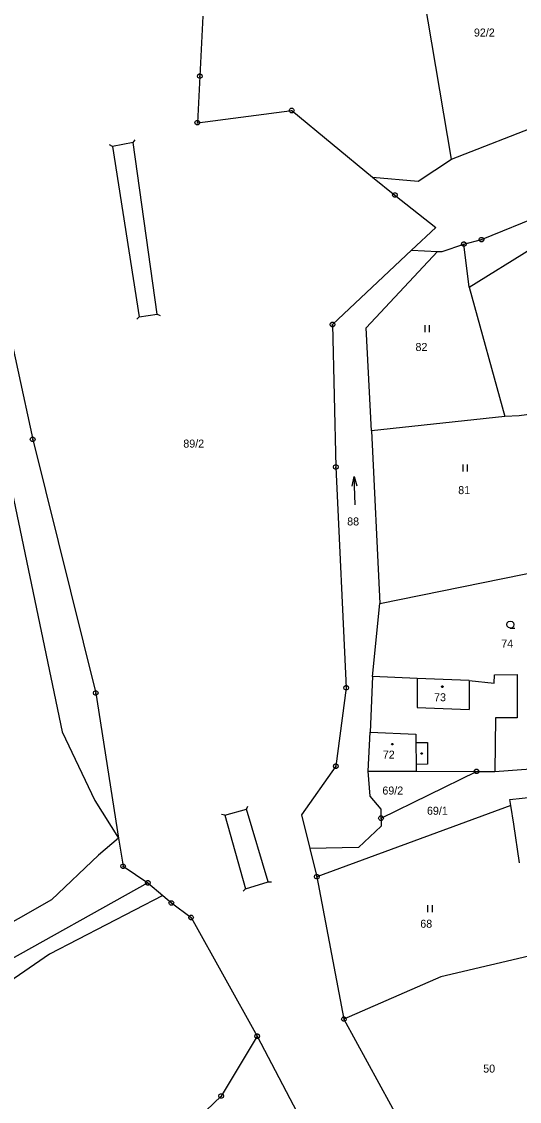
# Model space of a CAD drawing. Extents: x -812394 to -807601, y -1013098 to -1009266.
# Drawn here: x -809886.4 to -809780.5, y -1011042.4 to -1010813 of the extents above; entities that cross this region are included whole.
import ezdxf

# ---------------------------------------------------------------- set-up
doc = ezdxf.new("R2010")
doc.units = 0
for name, color, linetype in [('KN_HRANICE', 7, 'Continuous'), ('KN_KULTURY', 7, 'Continuous'), ('KN_MEZNIKY', 7, 'Continuous'), ('KN_PARCELY', 7, 'Continuous'), ('KN_SLUCKY', 7, 'Continuous')]:
    doc.layers.add(name, color=color, linetype=linetype)

# ---------------------------------------------------------------- blocks, each defined once
blk = doc.blocks.new('304')
blk.add_lwpolyline([(0, 0), (-0.38, 0.1), (-0.65, 0.37), (-0.75, 0.74), (-0.65, 1.11), (-0.38, 1.38), (-0.01, 1.48), (0.36, 1.38), (0.63, 1.11), (0.73, 0.73), (0.63, 0.35), (0.36, 0.08), (-0.02, -0.02), (0.98, -0.02)])
blk = doc.blocks.new('306')
for p, q in [((-0.5, 1.5), (-0.5, 0)), ((0.5, 0), (0.5, 1.5))]:
    blk.add_line(p, q)
blk = doc.blocks.new('802')
blk.add_line((-3, 0), (3, 0))
blk.add_lwpolyline([(1, 0.5), (3, 0), (1, -0.5)])
blk = doc.blocks.new('402')
blk.add_lwpolyline([(0.09, 0.15), (0.18, 0), (0.09, -0.15), (-0.09, -0.15), (-0.18, 0), (-0.09, 0.15), (0.09, 0.15)])
blk = doc.blocks.new('105')
blk.add_line((-0.12, 0), (0.12, 0))
blk.add_lwpolyline([(0.15, 0.48), (0.4, 0.3), (0.5, 0.01), (0.4, -0.28), (0.15, -0.46), (-0.16, -0.46), (-0.41, -0.28), (-0.51, 0.01), (-0.41, 0.3), (-0.16, 0.48), (0.15, 0.48)])
blk = doc.blocks.new('4201')
blk.add_line((0, 0), (-0.5, -0.5))

msp = doc.modelspace()

# ---------------------------------------------------------------- linework, layer by layer
at = {"layer": 'KN_HRANICE'}
for p, q in [((-809795, -1010842.25), (-809802.82, -1010795.47)), ((-809847.8, -1010811.91), (-809848.47, -1010824.63)), ((-809848.47, -1010824.63), (-809848.99, -1010834.52)), ((-809848.99, -1010834.52), (-809828.94, -1010831.94)), ((-809828.94, -1010831.94), (-809811.76, -1010846.11)), ((-809795, -1010842.25), (-809768.91, -1010832.11)), ((-809802.04, -1010846.92), (-809795, -1010842.25)), ((-809788.59, -1010859.35), (-809744.44, -1010841.28)), ((-809811.76, -1010846.11), (-809802.04, -1010846.92)), ((-809811.76, -1010846.11), (-809806.99, -1010849.89)), ((-809806.99, -1010849.89), (-809798.33, -1010856.76)), ((-809803.49, -1010861.61), (-809798.33, -1010856.76)), ((-809792.34, -1010860.31), (-809788.59, -1010859.35)), ((-809820.27, -1010877.38), (-809803.49, -1010861.61)), ((-809813.07, -1010878.06), (-809797.95, -1010861.84)), ((-809803.49, -1010861.61), (-809797.95, -1010861.84)), ((-809797.95, -1010861.84), (-809796.98, -1010861.88)), ((-809796.98, -1010861.88), (-809792.34, -1010860.31)), ((-809791.19, -1010869.46), (-809792.34, -1010860.31)), ((-809791.19, -1010869.46), (-809777.96, -1010861.22)), ((-809791.19, -1010869.46), (-809783.61, -1010896.9)), ((-809890.33, -1010872.36), (-809883.99, -1010901.78)), ((-809820.27, -1010877.38), (-809819.54, -1010907.65)), ((-809811.97, -1010899.94), (-809813.07, -1010878.06)), ((-809772.62, -1010895.72), (-809780.58, -1010896.79)), ((-809891.53, -1010897.94), (-809877.71, -1010963.9)), ((-809783.61, -1010896.9), (-809811.97, -1010899.94)), ((-809780.58, -1010896.79), (-809783.61, -1010896.9)), ((-809811.97, -1010899.94), (-809810.23, -1010936.6)), ((-809883.99, -1010901.78), (-809870.58, -1010955.65)), ((-809819.54, -1010907.65), (-809817.34, -1010954.54)), ((-809810.23, -1010936.6), (-809774.68, -1010929.4)), ((-809811.73, -1010952.15), (-809810.23, -1010936.6)), ((-809811.73, -1010952.15), (-809812.29, -1010963.93)), ((-809802.28, -1010952.55), (-809811.73, -1010952.15)), ((-809791.19, -1010953.02), (-809802.28, -1010952.55)), ((-809802.28, -1010952.55), (-809802.28, -1010958.7)), ((-809791.19, -1010953.02), (-809785.87, -1010953.57)), ((-809791.19, -1010953.02), (-809791.19, -1010959.17)), ((-809785.87, -1010953.57), (-809785.81, -1010951.78)), ((-809785.81, -1010951.78), (-809780.99, -1010951.72)), ((-809780.99, -1010951.72), (-809780.99, -1010960.93)), ((-809870.58, -1010955.65), (-809865.72, -1010986.44)), ((-809817.34, -1010954.54), (-809819.55, -1010971.19)), ((-809802.28, -1010958.7), (-809791.19, -1010959.17)), ((-809785.63, -1010960.93), (-809785.75, -1010972.3)), ((-809780.99, -1010960.93), (-809785.63, -1010960.93)), ((-809877.71, -1010963.9), (-809870.77, -1010978.5)), ((-809812.69, -1010972.27), (-809812.29, -1010963.93)), ((-809819.55, -1010971.19), (-809826.87, -1010981.55)), ((-809785.75, -1010972.3), (-809762.22, -1010970.5)), ((-809812.22, -1010977.58), (-809812.69, -1010972.27)), ((-809812.69, -1010972.27), (-809802.49, -1010972.27)), ((-809809.94, -1010982.24), (-809789.65, -1010972.3)), ((-809802.49, -1010972.27), (-809789.65, -1010972.3)), ((-809789.65, -1010972.3), (-809785.75, -1010972.3)), ((-809870.77, -1010978.5), (-809865.72, -1010986.44)), ((-809809.94, -1010980.34), (-809812.22, -1010977.58)), ((-809782.57, -1010978.23), (-809777.31, -1010977.72)), ((-809782.36, -1010979.51), (-809782.57, -1010978.23)), ((-809782.36, -1010979.51), (-809823.59, -1010994.66)), ((-809809.94, -1010982.24), (-809809.94, -1010980.34)), ((-809781.71, -1010983.51), (-809782.36, -1010979.51)), ((-809826.87, -1010981.55), (-809825.08, -1010988.69)), ((-809809.94, -1010982.24), (-809809.94, -1010983.94)), ((-809809.94, -1010983.94), (-809814.76, -1010988.43)), ((-809780.48, -1010991.7), (-809781.71, -1010983.51)), ((-809865.72, -1010986.44), (-809864.77, -1010992.44)), ((-809814.76, -1010988.43), (-809825.08, -1010988.69)), ((-809825.08, -1010988.69), (-809823.59, -1010994.66)), ((-809864.77, -1010992.44), (-809859.52, -1010995.97)), ((-809823.59, -1010994.66), (-809817.83, -1011024.91)), ((-809859.52, -1010995.97), (-809908, -1011022.99)), ((-809859.52, -1010995.97), (-809856.34, -1010998.68)), ((-809856.34, -1010998.68), (-809854.51, -1011000.24)), ((-809854.51, -1011000.24), (-809850.32, -1011003.33)), ((-809850.32, -1011003.33), (-809836.26, -1011028.53)), ((-809776.12, -1011010.98), (-809797.21, -1011015.92)), ((-809797.21, -1011015.92), (-809817.83, -1011024.91)), ((-809817.83, -1011024.91), (-809805.06, -1011048.21)), ((-809836.26, -1011028.53), (-809810.89, -1011076.81))]:
    msp.add_line(p, q, dxfattribs=at)
for points in [[(-809865.72, -1010986.44), (-809869.99, -1010990.08), (-809879.97, -1010999.54), (-809901.79, -1011011.97), (-809939.8, -1011020.34), (-809964.35, -1011020.31), (-809988.57, -1011017.29)], [(-809856.34, -1010998.68), (-809880.39, -1011011.09), (-809908.29, -1011030.22), (-809924.26, -1011031.19), (-809964.98, -1011028.8), (-809990.74, -1011026.75)], [(-809836.26, -1011028.53), (-809843.91, -1011041.24), (-809850.36, -1011047.46), (-809913.17, -1011066.15), (-809940.27, -1011066.63), (-809925.64, -1011129.13), (-809925.02, -1011131.63)]]:
    msp.add_lwpolyline(points, dxfattribs=at)
at = {"layer": 'KN_SLUCKY'}
for p, q in [((-809862.62, -1010838.73), (-809867.02, -1010839.54)), ((-809857.55, -1010875.16), (-809862.62, -1010838.73)), ((-809867.02, -1010839.54), (-809861.38, -1010875.75)), ((-809861.38, -1010875.75), (-809857.55, -1010875.16)), ((-809812.29, -1010963.93), (-809802.55, -1010964.39)), ((-809802.55, -1010964.39), (-809802.54, -1010966.18)), ((-809802.54, -1010966.18), (-809800.07, -1010966.17)), ((-809802.54, -1010966.18), (-809802.5, -1010970.8)), ((-809800.07, -1010966.17), (-809800.04, -1010970.79)), ((-809800.04, -1010970.79), (-809802.5, -1010970.8)), ((-809802.5, -1010970.8), (-809802.49, -1010972.27)), ((-809843.14, -1010981.57), (-809838.55, -1010980.29)), ((-809833.94, -1010995.74), (-809838.55, -1010980.29)), ((-809843.14, -1010981.57), (-809838.78, -1010997.2)), ((-809838.78, -1010997.2), (-809833.94, -1010995.74))]:
    msp.add_line(p, q, dxfattribs=at)

# ---------------------------------------------------------------- block references
at = {"layer": 'KN_KULTURY'}
for name, p in [('306', (-809800.11, -1010879.02)), ('306', (-809792.06, -1010908.62)), ('304', (-809782.45, -1010941.85)), ('402', (-809796.9, -1010954.29)), ('402', (-809807.54, -1010966.52)), ('402', (-809801.31, -1010968.47)), ('306', (-809799.54, -1011002.22))]:
    msp.add_blockref(name, p, dxfattribs=at)
at = {"layer": 'KN_KULTURY', "rotation": 91.845135}
msp.add_blockref('802', (-809815.56, -1010912.67), dxfattribs=at)
at = {"layer": 'KN_MEZNIKY'}
for p in [(-809848.47, -1010824.63), (-809828.94, -1010831.94), (-809848.99, -1010834.52), (-809806.99, -1010849.89), (-809788.59, -1010859.35), (-809792.34, -1010860.31), (-809820.27, -1010877.38), (-809883.99, -1010901.78), (-809819.54, -1010907.65), (-809870.58, -1010955.65), (-809817.34, -1010954.54), (-809819.55, -1010971.19), (-809789.65, -1010972.3), (-809809.94, -1010982.24), (-809864.77, -1010992.44), (-809823.59, -1010994.66), (-809859.52, -1010995.97), (-809854.51, -1011000.24), (-809850.32, -1011003.33), (-809817.83, -1011024.91), (-809836.26, -1011028.53), (-809843.91, -1011041.24)]:
    msp.add_blockref('105', p, dxfattribs=at)
at = {"layer": 'KN_SLUCKY'}
for p, rotation in [((-809862.62, -1010838.73), -169.72071599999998), ((-809867.02, -1010839.54), -71.80222900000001), ((-809857.55, -1010875.16), 110.92462900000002), ((-809838.55, -1010980.29), -161.41282800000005), ((-809843.14, -1010981.57), -54.89997400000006), ((-809833.94, -1010995.74), 131.608406)]:
    msp.add_blockref('4201', p, dxfattribs=dict(at, rotation=rotation))
for p in [(-809861.38, -1010875.75), (-809838.78, -1010997.2)]:
    msp.add_blockref('4201', p, dxfattribs=at)

# ---------------------------------------------------------------- texts
at = {"layer": 'KN_PARCELY'}
for s, p in [('92/2', (-809790.2, -1010816.22)), ('82', (-809802.62, -1010883)), ('89/2', (-809851.97, -1010903.52)), ('81', (-809793.54, -1010913.4)), ('88', (-809817.14, -1010920.06)), ('74', (-809784.39, -1010946)), ('73', (-809798.67, -1010957.39)), ('72', (-809809.57, -1010969.58)), ('69/2', (-809809.66, -1010977.21)), ('69/1', (-809800.18, -1010981.5)), ('68', (-809801.6, -1011005.5)), ('50', (-809788.23, -1011036.26))]:
    msp.add_text(s, height=1.7, dxfattribs=at).set_placement(p)

doc.saveas('drawing.dxf')
